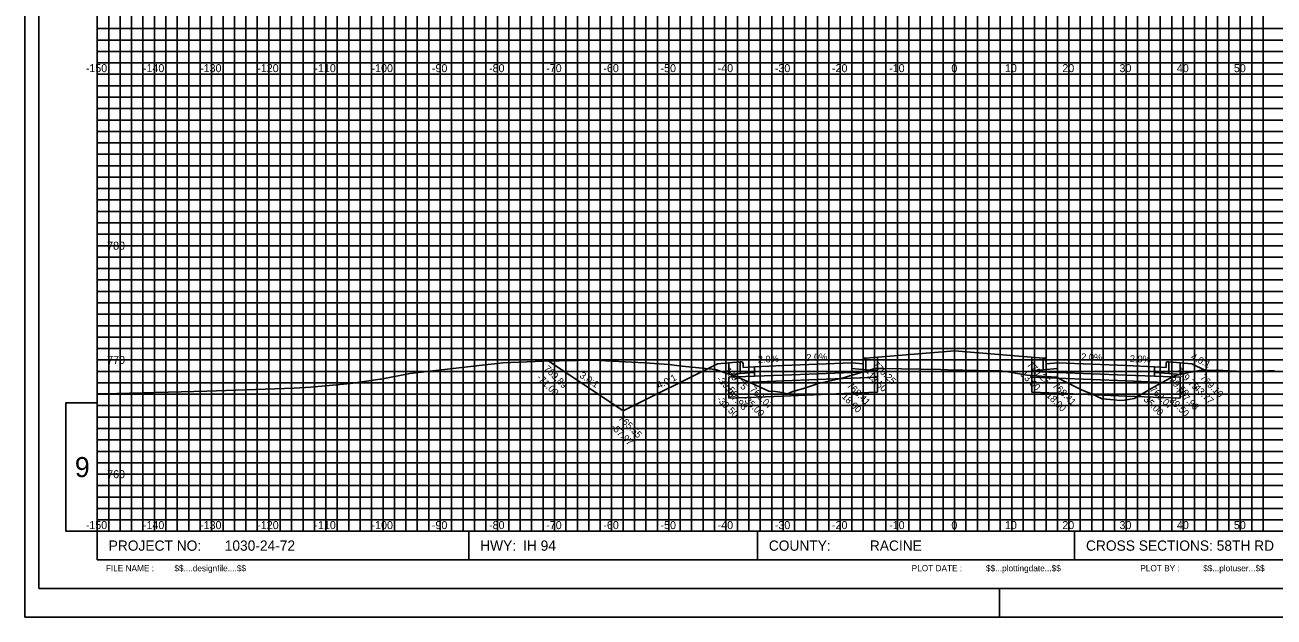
# Model space of a CAD drawing. Extents: x 578243 to 601557, y 174899 to 175559.
# Drawn here: x 599857.2 to 600075.7, y 175338.8 to 175442.4 of the extents above; entities that cross this region are included whole.
import ezdxf

# ---------------------------------------------------------------- set-up
doc = ezdxf.new("R2010")
doc.units = 0
for name, color, linetype in [('E_PROF_Grid', 7, 'Continuous'), ('E_PROF_GridMin', 7, 'Continuous'), ('P_CRDR_Label', 7, 'Continuous'), ('P_CRDR_Link', 7, 'Continuous'), ('P_E_XS_Ground', 7, 'Continuous'), ('P_XS_Text', 7, 'Continuous'), ('PLT_Sheet_Border', 7, 'Continuous'), ('PLT_Sheet_Info', 7, 'Continuous')]:
    doc.layers.add(name, color=color, linetype=linetype)

msp = doc.modelspace()

# ---------------------------------------------------------------- linework, layer by layer
at = {"layer": 'E_PROF_Grid'}
for p, q in [((599879.84, 175353.8), (599879.84, 175548.8)), ((599889.84, 175353.8), (599889.84, 175548.8)), ((599899.84, 175353.8), (599899.84, 175548.8)), ((599909.84, 175353.8), (599909.84, 175548.8)), ((599919.84, 175353.8), (599919.84, 175548.8)), ((599929.84, 175353.8), (599929.84, 175548.8)), ((599939.84, 175353.8), (599939.84, 175548.8)), ((599949.84, 175353.8), (599949.84, 175548.8)), ((599959.84, 175353.8), (599959.84, 175548.8)), ((599969.84, 175353.8), (599969.84, 175548.8)), ((599979.84, 175353.8), (599979.84, 175548.8)), ((599989.84, 175353.8), (599989.84, 175548.8)), ((599999.84, 175353.8), (599999.84, 175548.8)), ((600009.84, 175353.8), (600009.84, 175548.8)), ((600019.84, 175353.8), (600019.84, 175548.8)), ((600029.84, 175353.8), (600029.84, 175548.8)), ((600039.84, 175353.8), (600039.84, 175548.8)), ((600049.84, 175353.8), (600049.84, 175548.8)), ((600059.84, 175353.8), (600059.84, 175548.8)), ((600069.84, 175353.8), (600069.84, 175548.8)), ((599869.84, 175433.8), (600184.84, 175433.8)), ((599869.84, 175423.8), (600184.84, 175423.8)), ((599869.84, 175413.8), (600184.84, 175413.8)), ((599869.84, 175403.8), (600184.84, 175403.8)), ((599869.84, 175393.8), (600184.84, 175393.8)), ((599869.84, 175383.8), (600184.84, 175383.8)), ((599869.84, 175373.8), (600184.84, 175373.8)), ((599869.84, 175363.8), (600184.84, 175363.8))]:
    msp.add_line(p, q, dxfattribs=at)
at = {"layer": 'E_PROF_GridMin'}
for p, q in [((599871.84, 175353.8), (599871.84, 175548.8)), ((599873.84, 175353.8), (599873.84, 175548.8)), ((599875.84, 175353.8), (599875.84, 175548.8)), ((599877.84, 175353.8), (599877.84, 175548.8)), ((599881.84, 175353.8), (599881.84, 175548.8)), ((599883.84, 175353.8), (599883.84, 175548.8)), ((599885.84, 175353.8), (599885.84, 175548.8)), ((599887.84, 175353.8), (599887.84, 175548.8)), ((599891.84, 175353.8), (599891.84, 175548.8)), ((599893.84, 175353.8), (599893.84, 175548.8)), ((599895.84, 175353.8), (599895.84, 175548.8)), ((599897.84, 175353.8), (599897.84, 175548.8)), ((599901.84, 175353.8), (599901.84, 175548.8)), ((599903.84, 175353.8), (599903.84, 175548.8)), ((599905.84, 175353.8), (599905.84, 175548.8)), ((599907.84, 175353.8), (599907.84, 175548.8)), ((599911.84, 175353.8), (599911.84, 175548.8)), ((599913.84, 175353.8), (599913.84, 175548.8)), ((599915.84, 175353.8), (599915.84, 175548.8)), ((599917.84, 175353.8), (599917.84, 175548.8)), ((599921.84, 175353.8), (599921.84, 175548.8)), ((599923.84, 175353.8), (599923.84, 175548.8)), ((599925.84, 175353.8), (599925.84, 175548.8)), ((599927.84, 175353.8), (599927.84, 175548.8)), ((599931.84, 175353.8), (599931.84, 175548.8)), ((599933.84, 175353.8), (599933.84, 175548.8)), ((599935.84, 175353.8), (599935.84, 175548.8)), ((599937.84, 175353.8), (599937.84, 175548.8)), ((599941.84, 175353.8), (599941.84, 175548.8)), ((599943.84, 175353.8), (599943.84, 175548.8)), ((599945.84, 175353.8), (599945.84, 175548.8)), ((599947.84, 175353.8), (599947.84, 175548.8)), ((599951.84, 175353.8), (599951.84, 175548.8)), ((599953.84, 175353.8), (599953.84, 175548.8)), ((599955.84, 175353.8), (599955.84, 175548.8)), ((599957.84, 175353.8), (599957.84, 175548.8)), ((599961.84, 175353.8), (599961.84, 175548.8)), ((599963.84, 175353.8), (599963.84, 175548.8)), ((599965.84, 175353.8), (599965.84, 175548.8)), ((599967.84, 175353.8), (599967.84, 175548.8)), ((599971.84, 175353.8), (599971.84, 175548.8)), ((599973.84, 175353.8), (599973.84, 175548.8)), ((599975.84, 175353.8), (599975.84, 175548.8)), ((599977.84, 175353.8), (599977.84, 175548.8)), ((599981.84, 175353.8), (599981.84, 175548.8)), ((599983.84, 175353.8), (599983.84, 175548.8)), ((599985.84, 175353.8), (599985.84, 175548.8)), ((599987.84, 175353.8), (599987.84, 175548.8)), ((599991.84, 175353.8), (599991.84, 175548.8)), ((599993.84, 175353.8), (599993.84, 175548.8)), ((599995.84, 175353.8), (599995.84, 175548.8)), ((599997.84, 175353.8), (599997.84, 175548.8)), ((600001.84, 175353.8), (600001.84, 175548.8)), ((600003.84, 175353.8), (600003.84, 175548.8)), ((600005.84, 175353.8), (600005.84, 175548.8)), ((600007.84, 175353.8), (600007.84, 175548.8)), ((600011.84, 175353.8), (600011.84, 175548.8)), ((600013.84, 175353.8), (600013.84, 175548.8)), ((600015.84, 175353.8), (600015.84, 175548.8)), ((600017.84, 175353.8), (600017.84, 175548.8)), ((600021.84, 175353.8), (600021.84, 175548.8)), ((600023.84, 175353.8), (600023.84, 175548.8)), ((600025.84, 175353.8), (600025.84, 175548.8)), ((600027.84, 175353.8), (600027.84, 175548.8)), ((600031.84, 175353.8), (600031.84, 175548.8)), ((600033.84, 175353.8), (600033.84, 175548.8)), ((600035.84, 175353.8), (600035.84, 175548.8)), ((600037.84, 175353.8), (600037.84, 175548.8)), ((600041.84, 175353.8), (600041.84, 175548.8)), ((600043.84, 175353.8), (600043.84, 175548.8)), ((600045.84, 175353.8), (600045.84, 175548.8)), ((600047.84, 175353.8), (600047.84, 175548.8)), ((600051.84, 175353.8), (600051.84, 175548.8)), ((600053.84, 175353.8), (600053.84, 175548.8)), ((600055.84, 175353.8), (600055.84, 175548.8)), ((600057.84, 175353.8), (600057.84, 175548.8)), ((600061.84, 175353.8), (600061.84, 175548.8)), ((600063.84, 175353.8), (600063.84, 175548.8)), ((600065.84, 175353.8), (600065.84, 175548.8)), ((600067.84, 175353.8), (600067.84, 175548.8)), ((600071.84, 175353.8), (600071.84, 175548.8)), ((600073.84, 175353.8), (600073.84, 175548.8)), ((599869.84, 175441.8), (600184.84, 175441.8)), ((599869.84, 175439.8), (600184.84, 175439.8)), ((599869.84, 175437.8), (600184.84, 175437.8)), ((599869.84, 175435.8), (600184.84, 175435.8)), ((599869.84, 175431.8), (600184.84, 175431.8)), ((599869.84, 175429.8), (600184.84, 175429.8)), ((599869.84, 175427.8), (600184.84, 175427.8)), ((599869.84, 175425.8), (600184.84, 175425.8)), ((599869.84, 175421.8), (600184.84, 175421.8)), ((599869.84, 175419.8), (600184.84, 175419.8)), ((599869.84, 175417.8), (600184.84, 175417.8)), ((599869.84, 175415.8), (600184.84, 175415.8)), ((599869.84, 175411.8), (600184.84, 175411.8)), ((599869.84, 175409.8), (600184.84, 175409.8)), ((599869.84, 175407.8), (600184.84, 175407.8)), ((599869.84, 175405.8), (600184.84, 175405.8)), ((599869.84, 175401.8), (600184.84, 175401.8)), ((599869.84, 175399.8), (600184.84, 175399.8)), ((599869.84, 175397.8), (600184.84, 175397.8)), ((599869.84, 175395.8), (600184.84, 175395.8)), ((599869.84, 175391.8), (600184.84, 175391.8)), ((599869.84, 175389.8), (600184.84, 175389.8)), ((599869.84, 175387.8), (600184.84, 175387.8)), ((599869.84, 175385.8), (600184.84, 175385.8)), ((599869.84, 175381.8), (600184.84, 175381.8)), ((599869.84, 175379.8), (600184.84, 175379.8)), ((599869.84, 175377.8), (600184.84, 175377.8)), ((599869.84, 175375.8), (600184.84, 175375.8)), ((599869.84, 175371.8), (600184.84, 175371.8)), ((599869.84, 175369.8), (600184.84, 175369.8)), ((599869.84, 175367.8), (600184.84, 175367.8)), ((599869.84, 175365.8), (600184.84, 175365.8)), ((599869.84, 175361.8), (600184.84, 175361.8)), ((599869.84, 175359.8), (600184.84, 175359.8)), ((599869.84, 175357.8), (600184.84, 175357.8)), ((599869.84, 175355.8), (600184.84, 175355.8))]:
    msp.add_line(p, q, dxfattribs=at)
at = {"layer": 'P_CRDR_Link'}
for points in [[(600004.34, 175384.13), (600019.84, 175385.37)], [(600004.34, 175384.13), (600019.84, 175385.37)], [(600019.84, 175385.37), (600004.34, 175384.13)], [(600019.84, 175385.37), (600035.34, 175384.13)], [(600019.84, 175385.37), (600035.34, 175384.13)], [(600035.34, 175384.13), (600019.84, 175385.37)], [(599961.87, 175374.9), (599948.85, 175383.58)], [(599961.87, 175374.9), (599948.85, 175383.58)], [(599978.34, 175383.13), (599961.87, 175374.9)], [(599978.34, 175383.13), (599961.87, 175374.9)], [(599980.34, 175383.29), (599978.34, 175383.13)], [(599980.34, 175383.29), (599978.34, 175383.13)], [(599982.34, 175383.45), (599980.34, 175383.29)], [(599980.34, 175383.29), (599980.34, 175381.25)], [(599980.34, 175383.29), (599980.34, 175381.25)], [(599980.34, 175383.29), (599980.34, 175381.25)], [(599982.66, 175383.45), (599982.34, 175383.45)], [(599982.66, 175383.45), (599982.34, 175383.45)], [(599982.34, 175383.45), (599982.34, 175381.41)], [(599982.34, 175381.41), (599982.34, 175383.45)], [(599982.74, 175383.41), (599982.66, 175383.45)], [(599982.74, 175383.41), (599982.66, 175383.45)], [(599982.8, 175383.29), (599982.74, 175383.41)], [(599982.8, 175383.29), (599982.74, 175383.41)], [(599982.83, 175383.13), (599982.8, 175383.29)], [(599982.83, 175383.13), (599982.8, 175383.29)], [(599982.84, 175382.45), (599982.83, 175383.13)], [(599982.84, 175382.45), (599982.83, 175383.13)], [(600001.84, 175383.29), (599989.84, 175382.81)], [(600001.84, 175383.29), (600001.84, 175381.62)], [(600001.84, 175383.29), (600001.84, 175381.62)], [(600001.84, 175383.29), (600001.84, 175381.62)], [(600001.84, 175383.29), (600003.84, 175383.13)], [(600001.84, 175383.29), (600003.84, 175383.13)], [(600001.84, 175382.29), (600001.84, 175383.29)], [(600003.84, 175383.13), (600003.86, 175383.81)], [(600003.84, 175383.13), (600003.86, 175383.81)], [(600003.86, 175383.81), (600003.88, 175383.97)], [(600003.86, 175383.81), (600003.88, 175383.97)], [(600003.88, 175383.97), (600003.94, 175384.09)], [(600003.88, 175383.97), (600003.94, 175384.09)], [(600003.94, 175384.09), (600004.02, 175384.13)], [(600003.94, 175384.09), (600004.02, 175384.13)], [(600004.02, 175384.13), (600004.34, 175384.13)], [(600004.02, 175384.13), (600004.34, 175384.13)], [(600004.34, 175384.13), (600006.34, 175384.29)], [(600004.34, 175384.13), (600004.34, 175382.09)], [(600004.34, 175382.09), (600004.34, 175384.13)], [(600004.34, 175384.13), (600004.34, 175384.13)], [(600006.34, 175384.29), (600006.34, 175381.93)], [(600006.34, 175384.29), (600006.34, 175381.93)], [(600006.34, 175384.29), (600006.34, 175381.93)], [(600006.34, 175384.29), (600006.34, 175384.29)], [(600006.34, 175384.29), (600006.34, 175384.29)], [(600035.34, 175384.13), (600033.34, 175384.29)], [(600033.34, 175384.29), (600033.34, 175381.93)], [(600033.34, 175384.29), (600033.34, 175381.93)], [(600033.34, 175384.29), (600033.34, 175381.93)], [(600033.34, 175384.29), (600033.34, 175384.29)], [(600033.34, 175384.29), (600033.34, 175384.29)], [(600035.66, 175384.13), (600035.34, 175384.13)], [(600035.66, 175384.13), (600035.34, 175384.13)], [(600035.34, 175384.13), (600035.34, 175382.09)], [(600035.34, 175382.09), (600035.34, 175384.13)], [(600035.34, 175384.13), (600035.34, 175384.13)], [(600035.74, 175384.09), (600035.66, 175384.13)], [(600035.74, 175384.09), (600035.66, 175384.13)], [(600035.8, 175383.97), (600035.74, 175384.09)], [(600035.8, 175383.97), (600035.74, 175384.09)], [(600035.83, 175383.81), (600035.8, 175383.97)], [(600035.83, 175383.81), (600035.8, 175383.97)], [(600035.84, 175383.13), (600035.83, 175383.81)], [(600035.84, 175383.13), (600035.83, 175383.81)], [(600037.84, 175383.29), (600035.84, 175383.13)], [(600037.84, 175383.29), (600035.84, 175383.13)], [(600037.84, 175383.29), (600049.84, 175382.81)], [(600037.84, 175383.29), (600037.84, 175381.62)], [(600037.84, 175383.29), (600037.84, 175381.62)], [(600037.84, 175383.29), (600037.84, 175381.62)], [(600037.84, 175382.29), (600037.84, 175383.29)], [(600056.84, 175382.45), (600056.86, 175383.13)], [(600056.84, 175382.45), (600056.86, 175383.13)], [(600056.86, 175383.13), (600056.88, 175383.29)], [(600056.86, 175383.13), (600056.88, 175383.29)], [(600056.88, 175383.29), (600056.94, 175383.41)], [(600056.88, 175383.29), (600056.94, 175383.41)], [(600056.94, 175383.41), (600057.02, 175383.45)], [(600056.94, 175383.41), (600057.02, 175383.45)], [(600057.02, 175383.45), (600057.34, 175383.45)], [(600057.02, 175383.45), (600057.34, 175383.45)], [(600057.34, 175383.45), (600057.34, 175381.41)], [(600057.34, 175383.45), (600059.34, 175383.29)], [(600057.34, 175381.41), (600057.34, 175383.45)], [(600059.34, 175383.29), (600059.34, 175381.25)], [(600059.34, 175383.29), (600059.34, 175381.25)], [(600059.34, 175383.29), (600059.34, 175381.25)], [(600059.34, 175383.29), (600061.34, 175383.13)], [(600059.34, 175383.29), (600061.34, 175383.13)], [(600061.34, 175383.13), (600063.61, 175382)], [(600061.34, 175383.13), (600063.61, 175382)], [(599980.34, 175381.25), (599982.34, 175381.41)], [(599984.84, 175380.94), (599980.34, 175380.76)], [(599982.34, 175381.41), (599984.84, 175381.61)], [(599982.34, 175381.41), (599984.84, 175381.61)], [(599984.84, 175382.61), (599982.84, 175382.45)], [(599984.84, 175382.61), (599982.84, 175382.45)], [(599989.84, 175382.81), (599984.84, 175382.61)], [(599984.84, 175382.61), (599984.84, 175380.94)], [(599984.84, 175381.61), (599984.84, 175382.61)], [(599989.84, 175381.14), (599984.84, 175380.94)], [(599989.84, 175382.81), (599989.84, 175381.14)], [(599989.84, 175382.81), (599989.84, 175381.14)], [(600001.84, 175381.62), (599989.84, 175381.14)], [(599989.84, 175381.14), (599989.84, 175380.14)], [(599989.84, 175381.14), (599989.84, 175380.14)], [(600004.34, 175382.09), (600001.84, 175382.29)], [(600004.34, 175382.09), (600001.84, 175382.29)], [(600006.34, 175381.8), (600001.84, 175381.62)], [(600001.84, 175381.62), (600001.84, 175380.62)], [(600001.84, 175381.62), (600001.84, 175380.62)], [(600001.84, 175381.62), (600001.84, 175380.62)], [(600006.34, 175381.93), (600004.34, 175382.09)], [(600006.34, 175381.8), (600006.34, 175380.8)], [(600033.34, 175381.93), (600035.34, 175382.09)], [(600033.34, 175381.8), (600037.84, 175381.62)], [(600033.34, 175381.8), (600033.34, 175380.8)], [(600035.34, 175382.09), (600037.84, 175382.29)], [(600035.34, 175382.09), (600037.84, 175382.29)], [(600037.84, 175381.62), (600049.84, 175381.14)], [(600037.84, 175381.62), (600037.84, 175380.62)], [(600037.84, 175381.62), (600037.84, 175380.62)], [(600037.84, 175381.62), (600037.84, 175380.62)], [(600049.84, 175382.81), (600049.84, 175381.14)], [(600049.84, 175382.81), (600054.84, 175382.61)], [(600049.84, 175382.81), (600049.84, 175381.14)], [(600049.84, 175381.14), (600049.84, 175380.14)], [(600049.84, 175381.14), (600054.84, 175380.94)], [(600049.84, 175381.14), (600049.84, 175380.14)], [(600054.84, 175382.61), (600054.84, 175380.94)], [(600054.84, 175382.61), (600056.84, 175382.45)], [(600054.84, 175382.61), (600056.84, 175382.45)], [(600054.84, 175381.61), (600054.84, 175382.61)], [(600057.34, 175381.41), (600054.84, 175381.61)], [(600057.34, 175381.41), (600054.84, 175381.61)], [(600054.84, 175380.94), (600059.34, 175380.76)], [(600059.34, 175381.25), (600057.34, 175381.41)], [(599980.34, 175380.76), (599980.34, 175379.76)], [(599989.84, 175380.14), (599980.34, 175379.76)], [(599980.34, 175379.76), (599980.34, 175377.1)], [(600001.84, 175380.62), (599989.84, 175380.14)], [(599989.84, 175380.14), (599989.84, 175377.48)], [(599989.84, 175380.14), (599989.84, 175377.48)], [(600006.34, 175380.8), (600001.84, 175380.62)], [(600001.84, 175380.62), (600001.84, 175377.96)], [(600001.84, 175380.62), (600001.84, 175377.96)], [(600001.84, 175380.62), (600001.84, 175377.96)], [(600006.34, 175380.8), (600006.34, 175378.14)], [(600033.34, 175380.8), (600037.84, 175380.62)], [(600033.34, 175380.8), (600033.34, 175378.14)], [(600037.84, 175380.62), (600049.84, 175380.14)], [(600037.84, 175380.62), (600037.84, 175377.96)], [(600037.84, 175380.62), (600037.84, 175377.96)], [(600037.84, 175380.62), (600037.84, 175377.96)], [(600049.84, 175380.14), (600049.84, 175377.48)], [(600049.84, 175380.14), (600059.34, 175379.76)], [(600049.84, 175380.14), (600049.84, 175377.48)], [(600059.34, 175380.76), (600059.34, 175379.76)], [(600059.34, 175379.76), (600059.34, 175377.1)], [(599989.84, 175377.48), (599980.34, 175377.1)], [(600001.84, 175377.96), (599989.84, 175377.48)], [(600001.84, 175377.96), (600006.34, 175378.14)], [(600037.84, 175377.96), (600033.34, 175378.14)], [(600037.84, 175377.96), (600049.84, 175377.48)], [(600049.84, 175377.48), (600059.34, 175377.1)]]:
    msp.add_lwpolyline(points, dxfattribs=at)
at = {"layer": 'P_E_XS_Ground'}
msp.add_lwpolyline([(599869.84, 175377.84), (599870.99, 175377.86), (599889, 175378.31), (599904.27, 175378.84), (599907.22, 175379.03), (599909.77, 175379.26), (599914.15, 175379.69), (599919.31, 175380.42), (599919.51, 175380.45), (599919.81, 175380.52), (599924.5, 175381.41), (599935.17, 175382.68), (599940.8, 175383.32), (599947.86, 175383.56), (599956.49, 175383.78), (599965.67, 175383.29), (599969.85, 175383.01), (599972.16, 175382.72), (599978.03, 175382.11), (599981.41, 175380.98), (599982.47, 175380.55), (599985.19, 175379.3), (599987.36, 175378.36), (599988.52, 175378.26), (599989.26, 175378.17), (599989.84, 175378.06), (599990.61, 175377.86), (599991.52, 175378.25), (599993.43, 175378.79), (599995.66, 175379.58), (599995.77, 175379.62), (599995.77, 175379.62), (599995.77, 175379.62), (599999.95, 175380.54), (600005.89, 175382.28), (600006.04, 175382.32), (600006.22, 175382.32), (600007.19, 175382.3), (600017.37, 175382.1), (600019.84, 175382.04), (600021.29, 175382), (600026.05, 175381.9), (600028.01, 175381.88), (600029.49, 175381.64), (600032.55, 175381.11), (600036.74, 175380.83), (600037.69, 175380.79), (600038.64, 175380.28), (600042.17, 175378.5), (600043.8, 175377.86), (600045.68, 175377.02), (600047.74, 175376.83), (600048.74, 175376.71), (600049.56, 175376.78), (600051.28, 175377.05), (600052.2, 175377.58), (600054.9, 175379.16), (600056.03, 175379.8), (600058.33, 175381.03), (600059.78, 175381.39), (600062.67, 175381.98), (600065.62, 175382.03), (600070.34, 175381.75), (600074.77, 175381.88), (600075.81, 175381.9)], dxfattribs=at)
at = {"layer": 'PLT_Sheet_Border'}
for points in [[(599857.19, 175338.8), (600197.19, 175338.8), (600197.19, 175558.8), (599857.19, 175558.8)], [(599859.59, 175343.8), (600190.59, 175343.8), (600190.59, 175553.8), (599859.59, 175553.8)]]:
    msp.add_lwpolyline(points, close=True, dxfattribs=at)
at = {"layer": 'PLT_Sheet_Info'}
for p, q in [((599869.84, 175348.8), (599869.84, 175548.8)), ((599869.84, 175353.8), (600184.84, 175353.8)), ((599934.84, 175348.8), (599934.84, 175353.8)), ((599985.34, 175348.8), (599985.34, 175353.8)), ((600040.84, 175348.8), (600040.84, 175353.8)), ((599857.19, 175338.8), (599857.19, 175348.8)), ((599869.84, 175348.8), (600184.84, 175348.8)), ((600027.69, 175338.8), (600027.69, 175343.8)), ((599857.19, 175338.8), (599867.19, 175338.8)), ((600022.69, 175338.8), (600032.69, 175338.8))]:
    msp.add_line(p, q, dxfattribs=at)
msp.add_lwpolyline([(599869.84, 175376.3), (599864.34, 175376.3), (599864.34, 175353.8), (599869.84, 175353.8)], close=True, dxfattribs=at)

# ---------------------------------------------------------------- texts
at = {"layer": 'P_CRDR_Label'}
for s, rotation, p in [('2.0%', 2.2906, (599985.44, 175383.29)), ('2.0%', 2.2906, (599993.94, 175383.63)), ('770.25', 315, (600005.42, 175382.88)), ('770.25', 315, (600032.41, 175382.88)), ('2.0%', 357.7094, (600041.99, 175383.78)), ('2.0%', 357.7094, (600050.49, 175383.44)), ('4.0:1', 333.4349, (600061.07, 175383.98)), ('-71.00', 315, (599946.63, 175380.61)), ('-71.00', 315, (599946.63, 175380.61)), ('769.89', 315, (599947.92, 175382.17)), ('769.89', 315, (599947.92, 175382.17)), ('3.0:1', 326.3099, (599954.12, 175380.83)), ('4.0:1', 26.5651, (599968.14, 175378.74)), ('769.75', 315, (599979.41, 175381.88)), ('-13.50', 315, (600004.12, 175381.33)), ('13.50', 315, (600031.29, 175381.16)), ('769.75', 315, (600058.42, 175381.88)), ('769.10', 315, (600062.68, 175380.58)), ('769.10', 315, (600062.68, 175380.58)), ('-39.50', 315, (599978.12, 175380.33)), ('767.98', 315, (599979.42, 175378.35)), ('768.07', 315, (599983.92, 175378.53)), ('768.41', 315, (600000.91, 175379.21)), ('768.41', 315, (600000.91, 175379.21)), ('768.41', 315, (600000.91, 175379.21)), ('768.41', 315, (600036.91, 175379.21)), ('768.41', 315, (600036.91, 175379.21)), ('768.41', 315, (600036.91, 175379.21)), ('768.07', 315, (600053.91, 175378.53)), ('39.50', 315, (600057.31, 175380.14)), ('767.98', 315, (600058.41, 175378.35)), ('43.77', 315, (600061.63, 175378.8)), ('43.77', 315, (600061.63, 175378.8)), ('-39.50', 315, (599978.13, 175376.79)), ('-35.00', 315, (599982.63, 175376.97)), ('-18.00', 315, (599999.63, 175377.66)), ('-18.00', 315, (599999.63, 175377.66)), ('-18.00', 315, (599999.63, 175377.66)), ('18.00', 315, (600035.79, 175377.49)), ('18.00', 315, (600035.79, 175377.49)), ('18.00', 315, (600035.79, 175377.49)), ('35.00', 315, (600052.82, 175376.78)), ('39.50', 315, (600057.33, 175376.6)), ('-57.97', 315, (599959.66, 175371.93)), ('765.55', 315, (599960.95, 175373.48))]:
    msp.add_text(s, height=1.2, rotation=rotation, dxfattribs=at).set_placement(p)
at = {"layer": 'P_XS_Text'}
for s, p in [('-150', (599867.83, 175434.18)), ('-140', (599877.83, 175434.18)), ('-130', (599887.83, 175434.18)), ('-120', (599897.83, 175434.18)), ('-110', (599907.83, 175434.18)), ('-100', (599917.83, 175434.18)), ('-90', (599928.39, 175434.18)), ('-80', (599938.39, 175434.18)), ('-70', (599948.39, 175434.18)), ('-60', (599958.39, 175434.18)), ('-50', (599968.39, 175434.18)), ('-40', (599978.39, 175434.18)), ('-30', (599988.39, 175434.18)), ('-20', (599998.39, 175434.18)), ('-10', (600008.39, 175434.18)), ('0', (600019.28, 175434.18)), ('0', (600019.28, 175434.18)), ('10', (600028.66, 175434.18)), ('20', (600038.7, 175434.18)), ('30', (600048.7, 175434.18)), ('40', (600058.74, 175434.18)), ('50', (600068.71, 175434.18)), ('780', (599871.57, 175403.1)), ('770', (599871.57, 175383.1)), ('760', (599871.57, 175363.1)), ('-150', (599867.83, 175354.19)), ('-140', (599877.83, 175354.19)), ('-130', (599887.83, 175354.19)), ('-120', (599897.83, 175354.19)), ('-110', (599907.83, 175354.19)), ('-100', (599917.83, 175354.19)), ('-90', (599928.39, 175354.19)), ('-80', (599938.39, 175354.19)), ('-70', (599948.39, 175354.19)), ('-60', (599958.39, 175354.19)), ('-50', (599968.39, 175354.19)), ('-40', (599978.39, 175354.19)), ('-30', (599988.39, 175354.19)), ('-20', (599998.39, 175354.19)), ('-10', (600008.39, 175354.19)), ('0', (600019.28, 175354.19)), ('0', (600019.28, 175354.19)), ('10', (600028.66, 175354.19)), ('20', (600038.7, 175354.19)), ('30', (600048.7, 175354.19)), ('40', (600058.74, 175354.19)), ('50', (600068.71, 175354.19))]:
    msp.add_text(s, height=1.4, rotation=360, dxfattribs=at).set_placement(p)
at = {"layer": 'PLT_Sheet_Info'}
for s, height, p in [('9', 3.5, (599865.92, 175363.3)), ('PROJECT NO:', 1.8, (599871.84, 175350.4)), ('1030-24-72             ', 1.8, (599892.14, 175350.4)), ('HWY:', 1.8, (599936.84, 175350.4)), ('IH 94               ', 1.8, (599944.34, 175350.4)), ('COUNTY:', 1.8, (599987.34, 175350.4)), ('       RACINE       ', 1.8, (600000.34, 175350.4)), ('CROSS SECTIONS: 58TH RD                           ', 1.8, (600042.84, 175350.4)), ('FILE NAME :', 1.08, (599871.34, 175346.8))]:
    msp.add_text(s, height=height, dxfattribs=at).set_placement(p)
for s, p in [('$$....designfile....$$', (599883.34, 175346.8)), ('PLOT DATE :', (600012.34, 175346.8)), ('$$...plottingdate...$$', (600025.34, 175346.8)), ('PLOT BY :', (600052.34, 175346.8)), ('$$...plotuser...$$', (600063.34, 175346.8))]:
    msp.add_text(s, height=1.08, rotation=360, dxfattribs=at).set_placement(p)

doc.saveas('drawing.dxf')
